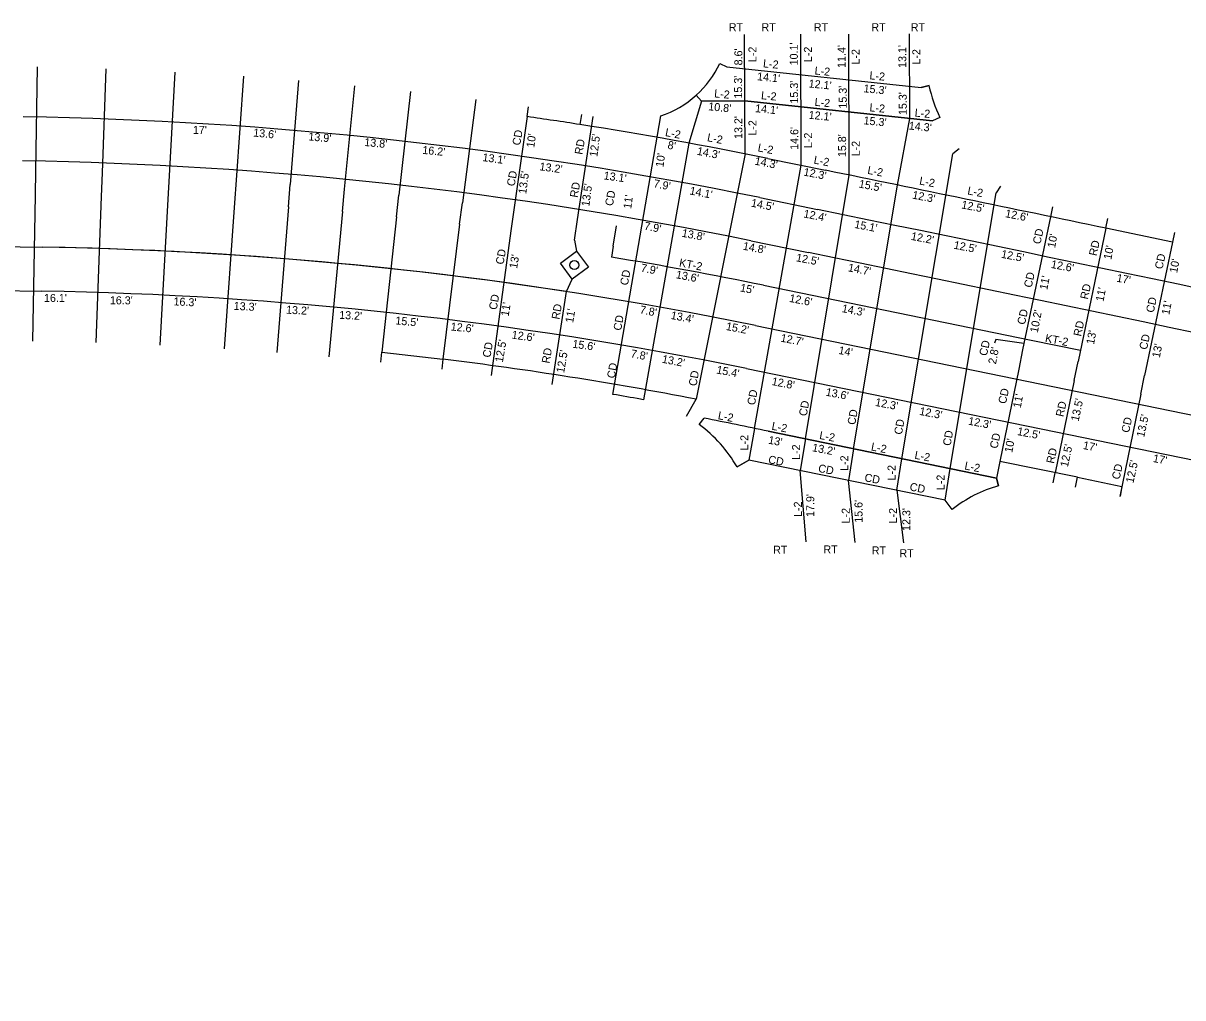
# Model space of a CAD drawing. Extents: x 4995357 to 4999033, y 3881202 to 3881750.
# Drawn here: x 4997475 to 4997764.8, y 3881461.9 to 3881705.4 of the extents above; entities that cross this region are included whole.
import ezdxf

# ---------------------------------------------------------------- set-up
doc = ezdxf.new("R2010")
doc.units = 0
for name, color, linetype in [('dsn3DCenterLine', 7, 'Continuous'), ('dsn3DCurbFormgrade', 7, 'Continuous'), ('dsn3DCurbTop', 7, 'Continuous'), ('dsn3DDitchFront', 7, 'Continuous'), ('dsn3DDNC', 7, 'Continuous'), ('dsn3DExistingPvmtBtm', 7, 'Continuous'), ('dsn3DGroundLineIntercept', 7, 'Continuous'), ('dsn3DIntakeWell', 7, 'Continuous')]:
    doc.layers.add(name, color=color, linetype=linetype)

msp = doc.modelspace()

# ---------------------------------------------------------------- linework, layer by layer
at = {"layer": 'dsn3DCenterLine'}
for p, q in [((4997718.11, 3881626.43), (4997717.74, 3881625.49)), ((4997725.12, 3881625.41), (4997718.11, 3881626.43))]:
    msp.add_line(p, q, dxfattribs=at)
at = {"layer": 'dsn3DCurbFormgrade'}
for p, q in [((4997478.51, 3881694.49), (4997478.08, 3881668.5)), ((4997494.8, 3881668.02), (4997495.76, 3881694)), ((4997511.55, 3881667.26), (4997512.95, 3881693.22)), ((4997528.29, 3881666.21), (4997530.13, 3881692.15)), ((4997543.82, 3881691.08), (4997541.76, 3881665.16)), ((4997555.35, 3881663.92), (4997557.91, 3881689.79)), ((4997571.81, 3881688.32), (4997568.89, 3881662.49)), ((4997643.2, 3881687.41), (4997644.54, 3881685.93)), ((4997588.12, 3881686.35), (4997584.79, 3881660.56)), ((4997600.96, 3881682.08), (4997597.64, 3881658.82)), ((4997613.56, 3881656.41), (4997617.51, 3881682.11)), ((4997477.96, 3881662.5), (4997477.35, 3881626.01)), ((4997493.23, 3881625.65), (4997494.58, 3881662.12)), ((4997509.27, 3881625.01), (4997511.24, 3881661.46)), ((4997525.3, 3881624.1), (4997527.88, 3881660.51)), ((4997541.31, 3881659.54), (4997538.43, 3881623.15)), ((4997554.8, 3881658.37), (4997551.42, 3881622.03)), ((4997568.28, 3881657.02), (4997564.66, 3881623.22)), ((4997584.1, 3881655.2), (4997579.93, 3881621.49)), ((4997612.77, 3881651.22), (4997613.31, 3881648.48)), ((4997610.79, 3881638.37), (4997612.26, 3881641.49)), ((4997723.83, 3881618.98), (4997719.11, 3881595.96)), ((4997737.69, 3881616.14), (4997732.98, 3881593.12)), ((4997754.35, 3881612.73), (4997749.12, 3881587.21))]:
    msp.add_line(p, q, dxfattribs=at)
at = {"layer": 'dsn3DCurbTop'}
for p, q in [((4997655.43, 3881672.79), (4997643.24, 3881611.48)), ((4997694.65, 3881596.61), (4997707.35, 3881672.78)), ((4997708.93, 3881674.02), (4997707.35, 3881672.78)), ((4997657.83, 3881604.18), (4997669.48, 3881669.93)), ((4997661.14, 3881671.64), (4997675.53, 3881668.69)), ((4997478.08, 3881668.5), (4997477.96, 3881662.5)), ((4997494.58, 3881662.12), (4997494.8, 3881668.02)), ((4997511.24, 3881661.46), (4997511.55, 3881667.26)), ((4997670.5, 3881601.56), (4997681.49, 3881667.47)), ((4997527.88, 3881660.51), (4997528.29, 3881666.21)), ((4997541.31, 3881659.54), (4997541.76, 3881665.16)), ((4997554.8, 3881658.37), (4997555.35, 3881663.92)), ((4997682.57, 3881599.09), (4997693.56, 3881664.98)), ((4997719.27, 3881664.73), (4997718.22, 3881663.03)), ((4997568.28, 3881657.02), (4997568.89, 3881662.49)), ((4997584.1, 3881655.2), (4997584.79, 3881660.56)), ((4997706.73, 3881594.14), (4997718.22, 3881663.03)), ((4997597.64, 3881658.82), (4997596.92, 3881653.53)), ((4997732.25, 3881659.53), (4997731.74, 3881657.08)), ((4997612.77, 3881651.22), (4997613.56, 3881656.41)), ((4997622.48, 3881649.68), (4997623.32, 3881654.81)), ((4997731.74, 3881657.08), (4997724.82, 3881623.8)), ((4997596.92, 3881653.53), (4997591.96, 3881617.37)), ((4997745.61, 3881654.19), (4997738.67, 3881620.91)), ((4997656.92, 3881651.06), (4997671.31, 3881648.11)), ((4997762.28, 3881650.7), (4997755.31, 3881617.43)), ((4997607.22, 3881615.15), (4997610.79, 3881638.37)), ((4997724.82, 3881623.79), (4997723.83, 3881618.98)), ((4997737.69, 3881616.14), (4997738.67, 3881620.91)), ((4997754.35, 3881612.73), (4997755.31, 3881617.43)), ((4997640.78, 3881607.27), (4997643.24, 3881611.48)), ((4997644, 3881605.15), (4997645.19, 3881606.75)), ((4997653.44, 3881594.57), (4997656.4, 3881596.28)), ((4997705.41, 3881586.24), (4997656.4, 3881596.28)), ((4997718.79, 3881589.85), (4997718.26, 3881591.78)), ((4997707.22, 3881583.96), (4997705.41, 3881586.24))]:
    msp.add_line(p, q, dxfattribs=at)
for centre, radius, start, end in [((4997458.39, 3880682.19), 989, 78.42004, 89.04825), ((4993658.81, 3862065.98), 20010, 78.215106, 78.420039)]:
    msp.add_arc(centre, radius, start, end, dxfattribs=at)
at = {"layer": 'dsn3DDitchFront'}
for p, q in [((4997660.08, 3881639.95), (4997726.97, 3881626.25)), ((4997726.97, 3881626.25), (4997739.26, 3881623.73))]:
    msp.add_line(p, q, dxfattribs=at)
msp.add_arc((4997463.81, 3880682.1), 977.75, 78.42004, 80.68708, dxfattribs=at)
at = {"layer": 'dsn3DDNC'}
for p, q in [((4997655.38, 3881686.01), (4997655.32, 3881702.61)), ((4997669.48, 3881669.93), (4997669.35, 3881702.66)), ((4997681.49, 3881667.47), (4997681.35, 3881702.7)), ((4997696.6, 3881681.64), (4997696.52, 3881702.76)), ((4997655.43, 3881672.79), (4997655.38, 3881686.01)), ((4997693.56, 3881664.98), (4997696.6, 3881681.64)), ((4997659.13, 3881661.84), (4997673.52, 3881658.89)), ((4996408.52, 3881656.27), (4997479.7, 3881638.47)), ((4997364.99, 3881651.38), (4997479.89, 3881649.47)), ((4997658.03, 3881629.91), (4998165.9, 3881525.84)), ((4997655.82, 3881619.13), (4998163.69, 3881515.07)), ((4997657.82, 3881604.19), (4997656.4, 3881596.28)), ((4997718.26, 3881591.78), (4997661.22, 3881603.46)), ((4997670.5, 3881601.56), (4997669.18, 3881593.67)), ((4997682.57, 3881599.09), (4997681.26, 3881591.19)), ((4997693.33, 3881588.72), (4997694.65, 3881596.61)), ((4997705.41, 3881586.24), (4997706.73, 3881594.14)), ((4997719.11, 3881595.96), (4997718.26, 3881591.78)), ((4997738.55, 3881591.97), (4997719.11, 3881595.96)), ((4997670.7, 3881575.82), (4997669.18, 3881593.67)), ((4997682.94, 3881575.71), (4997681.26, 3881591.19)), ((4997693.33, 3881588.72), (4997695.01, 3881575.61))]:
    msp.add_line(p, q, dxfattribs=at)
for centre, radius, start, end in [((4997458.39, 3880682.19), 1000, 78.42004, 89.04825), ((4997458.39, 3880682.19), 1010, 78.42004, 81.1288), ((4993658.81, 3862065.98), 20000, 76.008501, 78.420039), ((4997463.81, 3880682.1), 967.5, 78.42004, 89.04825), ((4997463.81, 3880682.1), 967.5, 81.26215, 89.04825), ((4993658.81, 3862065.98), 19989, 76.008501, 78.420039), ((4997463.81, 3880682.1), 956.5, 78.42004, 89.04825), ((4997463.81, 3880682.1), 946.54, 79.07295, 82.95342), ((4997463.81, 3880682.1), 942.27, 77.90919, 78.90205)]:
    msp.add_arc(centre, radius, start, end, dxfattribs=at)
at = {"layer": 'dsn3DExistingPvmtBtm'}
for p, q in [((4997600.96, 3881682.08), (4997601.31, 3881684.56)), ((4997614.54, 3881682.58), (4997614.15, 3881680.11)), ((4997745.61, 3881654.19), (4997746.12, 3881656.64)), ((4997762.28, 3881650.7), (4997745.61, 3881654.19)), ((4997762.8, 3881653.16), (4997762.28, 3881650.7)), ((4997732.46, 3881590.63), (4997732.98, 3881593.12))]:
    msp.add_line(p, q, dxfattribs=at)
msp.add_lwpolyline([(4997609.29, 3881645.51), (4997613.31, 3881648.48), (4997616.28, 3881644.46), (4997612.26, 3881641.49)], close=True, dxfattribs=at)
for points in [[(4997564.39, 3881620.74), (4997564.66, 3881623.23), (4997579.93, 3881621.49), (4997579.63, 3881619.02)], [(4997738.05, 3881589.52), (4997738.55, 3881591.97), (4997749.63, 3881589.7), (4997749.16, 3881587.25)]]:
    msp.add_lwpolyline(points, dxfattribs=at)
msp.add_circle((4997612.78, 3881644.98), 1.13, dxfattribs=at)
msp.add_arc((4997458.39, 3880682.19), 1010, 81.1288, 81.88535, dxfattribs=at)
at = {"layer": 'dsn3DGroundLineIntercept'}
for p, q in [((4997649.1, 3881695.38), (4997650.91, 3881694.53)), ((4997650.91, 3881694.53), (4997699.46, 3881689.38)), ((4997701.41, 3881689.82), (4997699.46, 3881689.38)), ((4997644.54, 3881685.93), (4997641.41, 3881675.47)), ((4997644.54, 3881685.93), (4997655.38, 3881686.01)), ((4997655.38, 3881686.01), (4997702.3, 3881681.03)), ((4997622.41, 3881612.69), (4997634.37, 3881682.27)), ((4997704.12, 3881681.87), (4997702.3, 3881681.03)), ((4997641.41, 3881675.47), (4997630.04, 3881611.35)), ((4997622.48, 3881649.68), (4997622.04, 3881646.97))]:
    msp.add_line(p, q, dxfattribs=at)
at = {"layer": 'dsn3DIntakeWell'}
for p, q in [((4997622.41, 3881612.69), (4997634.37, 3881682.27)), ((4997644, 3881605.15), (4997645.19, 3881606.75))]:
    msp.add_line(p, q, dxfattribs=at)
for points in [[(4997649.1, 3881695.38), (4997650.91, 3881694.53), (4997699.46, 3881689.38), (4997701.41, 3881689.82)], [(4997643.2, 3881687.41), (4997644.54, 3881685.93), (4997641.41, 3881675.47), (4997630.04, 3881611.35)], [(4997704.12, 3881681.87), (4997702.3, 3881681.03), (4997655.38, 3881686.01), (4997644.54, 3881685.93), (4997643.2, 3881687.41)], [(4997661.23, 3881603.46), (4997718.26, 3881591.78), (4997718.79, 3881589.85)], [(4997707.22, 3881583.96), (4997705.41, 3881586.24), (4997656.4, 3881596.28), (4997653.44, 3881594.57)]]:
    msp.add_lwpolyline(points, dxfattribs=at)
for centre, radius, start, end in [((4997626.47, 3881705.99), 25, 312.0044, 334.8837), ((4997740.41, 3881698.69), 40, 192.8118, 204.8657), ((4997626.47, 3881705.99), 25, 288.4316, 312.0044), ((4997463.81, 3880682.1), 944, 79.90443, 80.32832), ((4997623.15, 3881577.03), 35, 78.6601, 79.9044), ((4997463.81, 3880682.1), 942.27, 77.90655, 78.90205), ((4997623.15, 3881577.03), 35, 30.0774, 53.4481), ((4997727.45, 3881558.52), 32.5, 105.4501, 128.4844)]:
    msp.add_arc(centre, radius, start, end, dxfattribs=at)

# ---------------------------------------------------------------- texts
at = {"layer": 'dsn3DCenterLine'}
for s, p in [('RT', (4997651.37, 3881703.42)), ('RT', (4997659.54, 3881703.42)), ('RT', (4997672.63, 3881703.42)), ('RT', (4997687, 3881703.42)), ('RT', (4997696.85, 3881703.42)), ("17'", (4997517.43, 3881677.77)), ("16.1'", (4997480.2, 3881635.78)), ("16.3'", (4997496.67, 3881635.19)), ('RT', (4997662.45, 3881572.88)), ('RT', (4997675.02, 3881572.96)), ('RT', (4997687.11, 3881572.71)), ('RT', (4997694.03, 3881572.01))]:
    msp.add_text(s, height=2, dxfattribs=at).set_placement(p)
for s, rotation, p in [("8.6'", 90, (4997654.76, 3881694.88)), ('L-2', 90, (4997658.28, 3881695.7)), ("10.1'", 90, (4997668.62, 3881694.88)), ('L-2', 90, (4997672.14, 3881695.7)), ("11.4'", 90, (4997680.55, 3881694.25)), ('L-2', 90, (4997684.07, 3881695.08)), ("13.1'", 90, (4997695.73, 3881694.25)), ('L-2', 90, (4997699.25, 3881695.08)), ('L-2', 354.5621, (4997659.86, 3881694.41)), ("14.1'", 354.4502, (4997658.38, 3881691.18)), ('L-2', 354.5621, (4997672.75, 3881692.63)), ('L-2', 354.5621, (4997686.47, 3881691.42)), ("15.3'", 90, (4997654.69, 3881686.59)), ("15.3'", 90, (4997668.68, 3881685.34)), ("12.1'", 354.4502, (4997671.26, 3881689.39)), ("15.3'", 90, (4997680.86, 3881684.09)), ("15.3'", 354.4502, (4997684.99, 3881688.18)), ('L-2', 354.5621, (4997647.65, 3881686.91)), ('L-2', 354.5621, (4997659.36, 3881686.45)), ('L-2', 354.5621, (4997672.75, 3881684.8)), ("15.3'", 90, (4997695.85, 3881682.47)), ("10.8'", 354.4502, (4997646.17, 3881683.68)), ("14.1'", 354.4502, (4997657.88, 3881683.21)), ('L-2', 354.5621, (4997686.47, 3881683.42)), ('L-2', 354.5621, (4997697.77, 3881682.11)), ("13.2'", 90, (4997654.76, 3881676.5)), ('L-2', 90, (4997658.28, 3881677.33)), ("12.1'", 354.4502, (4997671.26, 3881681.57)), ("15.3'", 354.4502, (4997684.99, 3881680.18)), ("13.6'", 354.664, (4997532.44, 3881677.12)), ("13.9'", 354.664, (4997546.22, 3881676.17)), ('CD', 79.9188, (4997599.2, 3881674.78)), ('L-2', 349.2338, (4997635.35, 3881677.26)), ("14.6'", 90, (4997668.74, 3881673.78)), ('L-2', 90, (4997672.18, 3881674.22)), ("14.3'", 354.4502, (4997696.29, 3881678.87)), ("13.8'", 354.664, (4997560.2, 3881674.76)), ("10'", 82.3022, (4997602.74, 3881674.23)), ('RD', 79.9188, (4997614.76, 3881672.48)), ("12.5'", 82.3022, (4997618.5, 3881671.93)), ("8'", 349.1219, (4997635.94, 3881674.1)), ('L-2', 349.2338, (4997645.84, 3881675.97)), ('L-2', 349.2338, (4997658.49, 3881673.43)), ("15.8'", 90, (4997680.69, 3881671.96)), ('L-2', 90, (4997684.1, 3881672.16)), ("16.2'", 354.664, (4997574.7, 3881672.79)), ("13.1'", 352.2534, (4997589.71, 3881670.99)), ("10'", 82.3022, (4997635.03, 3881669.35)), ("14.3'", 349.1219, (4997643.29, 3881672.58)), ('L-2', 349.2338, (4997672.48, 3881670.38)), ("13.2'", 352.2534, (4997603.97, 3881668.7)), ("14.3'", 349.1219, (4997657.73, 3881670.11)), ('L-2', 349.2338, (4997685.91, 3881667.81)), ('CD', 79.9188, (4997597.82, 3881664.57)), ("13.5'", 82.3022, (4997600.72, 3881662.66)), ("13.1'", 352.2534, (4997620, 3881666.42)), ("7.9'", 349.1219, (4997632.44, 3881664.48)), ("12.3'", 349.1219, (4997669.93, 3881667.38)), ('L-2', 349.2338, (4997698.88, 3881665.15)), ('RD', 79.9188, (4997613.58, 3881661.73)), ("13.5'", 82.3022, (4997616.49, 3881659.54)), ('CD', 79.9188, (4997622.38, 3881659.65)), ("14.1'", 349.1219, (4997641.46, 3881662.67)), ("15.5'", 349.1219, (4997683.75, 3881664.4)), ("12.3'", 349.1219, (4997697.12, 3881661.63)), ('L-2', 349.2338, (4997710.91, 3881662.68)), ("11'", 82.3022, (4997626.97, 3881658.95)), ("14.5'", 349.1219, (4997656.81, 3881659.63)), ("12.5'", 349.171, (4997709.39, 3881659.18)), ("12.4'", 349.1219, (4997669.93, 3881656.92)), ("12.6'", 349.171, (4997720.34, 3881656.98)), ("7.9'", 349.1219, (4997630.09, 3881653.86)), ("15.1'", 349.171, (4997682.65, 3881654.29)), ("13.8'", 349.1219, (4997639.5, 3881652.1)), ("12.2'", 349.171, (4997696.79, 3881651.32)), ('CD', 77.6448, (4997729.25, 3881650.09)), ("10'", 79.1851, (4997732.91, 3881649.16)), ("14.8'", 349.171, (4997654.77, 3881648.86)), ("12.5'", 349.171, (4997707.47, 3881649.11)), ('RD', 77.6448, (4997743.3, 3881647.16)), ("10'", 79.1851, (4997746.97, 3881646.24)), ('CD', 79.9188, (4997595.04, 3881645.01)), ("13'", 80.3374, (4997598.44, 3881644.01)), ('KT-2', 349.1219, (4997638.84, 3881644.69)), ("12.5'", 349.1219, (4997668.06, 3881645.97)), ("12.5'", 349.171, (4997719.32, 3881646.85)), ("12.6'", 349.171, (4997731.78, 3881644.31)), ('CD', 77.6448, (4997759.75, 3881643.83)), ("10'", 79.1851, (4997763.42, 3881642.91)), ('CD', 79.9188, (4997626.14, 3881639.82)), ("7.9'", 349.1219, (4997629.25, 3881643.39)), ("13.6'", 349.1219, (4997638.03, 3881641.73)), ("14.7'", 349.171, (4997681.05, 3881643.46)), ('CD', 77.6448, (4997727.05, 3881639.23)), ("11'", 79.1851, (4997730.96, 3881638.68)), ("17'", 349.171, (4997748.17, 3881640.87)), ('CD', 79.9188, (4997593.35, 3881633.7)), ("15'", 349.171, (4997654.08, 3881638.43)), ("12.6'", 349.1219, (4997666.38, 3881635.82)), ('RD', 77.6448, (4997741.11, 3881636.3)), ("11'", 79.1851, (4997745.01, 3881635.76)), ("16.3'", 357.0514, (4997512.54, 3881634.94)), ("13.3'", 357.0514, (4997527.58, 3881633.82)), ("13.2'", 357.0514, (4997540.67, 3881632.86)), ("11'", 80.3374, (4997596.32, 3881632.07)), ('RD', 79.9188, (4997609.01, 3881631.3)), ("7.8'", 349.1219, (4997629, 3881632.95)), ("14.3'", 349.171, (4997679.51, 3881633.27)), ('CD', 77.6448, (4997757.56, 3881632.97)), ("11'", 79.1851, (4997761.46, 3881632.43)), ("13.2'", 357.0514, (4997553.95, 3881631.58)), ("15.5'", 354.5387, (4997567.97, 3881630.2)), ("11'", 80.3374, (4997612.45, 3881630.45)), ('CD', 79.9188, (4997624.46, 3881628.51)), ("13.4'", 349.1219, (4997636.75, 3881631.56)), ('CD', 77.6448, (4997725.37, 3881629.98)), ("10.2'", 79.1851, (4997728.59, 3881627.97)), ("12.6'", 354.5387, (4997581.79, 3881628.67)), ("15.2'", 349.171, (4997650.55, 3881628.8)), ('RD', 77.6448, (4997739.42, 3881627.06)), ("13'", 79.1851, (4997742.64, 3881625.04)), ("12.5'", 80.3374, (4997594.88, 3881620.57)), ("12.6'", 352.3805, (4997597.02, 3881626.65)), ("15.6'", 352.3805, (4997612.19, 3881624.37)), ("12.7'", 349.1219, (4997664.2, 3881625.89)), ('CD', 77.6448, (4997715.86, 3881622.18)), ('KT-2', 349.1219, (4997730.31, 3881625.83)), ('CD', 77.6448, (4997755.87, 3881623.73)), ('CD', 79.9188, (4997591.76, 3881621.77)), ('RD', 79.9188, (4997606.54, 3881620.31)), ("12.5'", 80.3374, (4997610.2, 3881617.94)), ("7.8'", 349.171, (4997626.73, 3881621.99)), ("14'", 349.171, (4997678.68, 3881622.82)), ("2.8'", 79.1851, (4997718.13, 3881620.11)), ("13'", 79.1851, (4997759.09, 3881621.71)), ('CD', 79.9188, (4997622.86, 3881616.58)), ("13.2'", 349.171, (4997634.55, 3881620.62)), ('CD', 79.9188, (4997643.28, 3881614.64)), ("15.4'", 349.171, (4997648.16, 3881617.94)), ("12.8'", 349.171, (4997661.99, 3881615.05)), ("13.6'", 349.171, (4997675.48, 3881612.39)), ('CD', 79.9188, (4997657.9, 3881609.89)), ("12.3'", 349.171, (4997687.84, 3881609.84)), ('CD', 77.6448, (4997720.62, 3881610.19)), ("11'", 79.1851, (4997724.33, 3881609.18)), ("13.5'", 77.6448, (4997738.79, 3881605.82)), ('L-2', 349.171, (4997648.53, 3881606.52)), ('CD', 79.9188, (4997670.83, 3881607.14)), ('CD', 79.9188, (4997682.95, 3881604.96)), ("12.3'", 349.171, (4997698.89, 3881607.6)), ('RD', 77.6448, (4997735, 3881606.95)), ('L-2', 349.171, (4997661.96, 3881603.89)), ('CD', 79.9188, (4997694.63, 3881602.52)), ("12.3'", 349.171, (4997711.08, 3881605.16)), ('CD', 77.6448, (4997751.4, 3881602.98)), ("13.5'", 77.6448, (4997755.18, 3881601.85)), ('L-2', 349.171, (4997673.89, 3881601.58)), ('CD', 79.9188, (4997706.8, 3881599.71)), ('CD', 77.6448, (4997718.5, 3881599.01)), ("12.5'", 349.171, (4997723.35, 3881602.56)), ('L-2', 90.0116, (4997656.26, 3881598.69)), ("13'", 349.171, (4997661.11, 3881600.4)), ('L-2', 90.0116, (4997669.19, 3881596.32)), ("13.2'", 349.171, (4997672.09, 3881598.51)), ('L-2', 349.171, (4997686.81, 3881598.71)), ("10'", 79.1851, (4997722.21, 3881598)), ("12.5'", 77.6448, (4997736.11, 3881594.39)), ("17'", 349.171, (4997739.78, 3881599.07)), ('CD', 349.171, (4997661.11, 3881595.52)), ('L-2', 90.0116, (4997681.24, 3881593.57)), ('L-2', 349.171, (4997697.68, 3881596.64)), ('RD', 77.6448, (4997732.64, 3881595.28)), ("17'", 349.171, (4997757.28, 3881595.82)), ('CD', 349.171, (4997673.6, 3881593.33)), ('L-2', 90.0116, (4997693.05, 3881591.19)), ('L-2', 349.171, (4997710.17, 3881593.96)), ('CD', 77.6448, (4997749.03, 3881591.31)), ("12.5'", 77.6448, (4997752.5, 3881590.41)), ('CD', 349.171, (4997685.16, 3881591.02)), ('L-2', 90.0116, (4997705.29, 3881588.76)), ('CD', 349.171, (4997696.46, 3881588.71)), ('L-2', 90.0116, (4997669.63, 3881582.07)), ("17.9'", 90.0116, (4997672.73, 3881582.07)), ("15.6'", 90.0116, (4997684.79, 3881580.61)), ('L-2', 90.0116, (4997681.6, 3881580.45)), ('L-2', 90.0116, (4997693.41, 3881580.45)), ("12.3'", 90.0116, (4997696.75, 3881578.57))]:
    msp.add_text(s, height=2, rotation=rotation, dxfattribs=at).set_placement(p)

doc.saveas('drawing.dxf')
